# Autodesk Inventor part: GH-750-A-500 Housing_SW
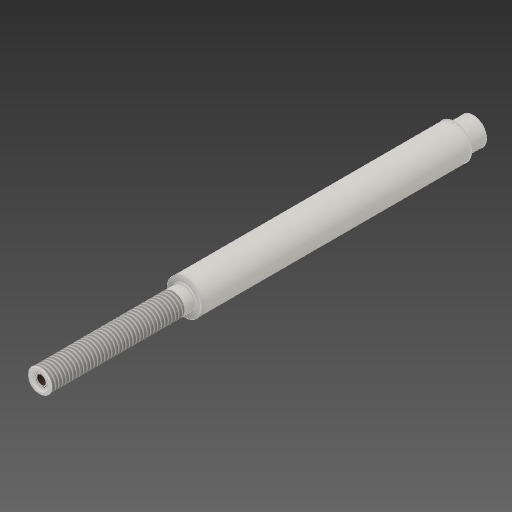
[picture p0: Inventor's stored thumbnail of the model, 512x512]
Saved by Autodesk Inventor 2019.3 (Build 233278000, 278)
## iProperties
Created: 2018-11
Part Number: GH-750-A-500 Housing_SW
Material: Generic
Document SubType Name: Modeling
Designer: Justin
Density: 1 g/cm^3
Appearance: Default
Author: Justin
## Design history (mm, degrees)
node "Assembly1"
body "Solid1"
node "Part1:1"
node "Part2:1"
body "Solid2"
node "Part3:1"
body "Solid3"
node "Part4:1"
body "Solid4"
node "Part5:1"
body "Solid5"
